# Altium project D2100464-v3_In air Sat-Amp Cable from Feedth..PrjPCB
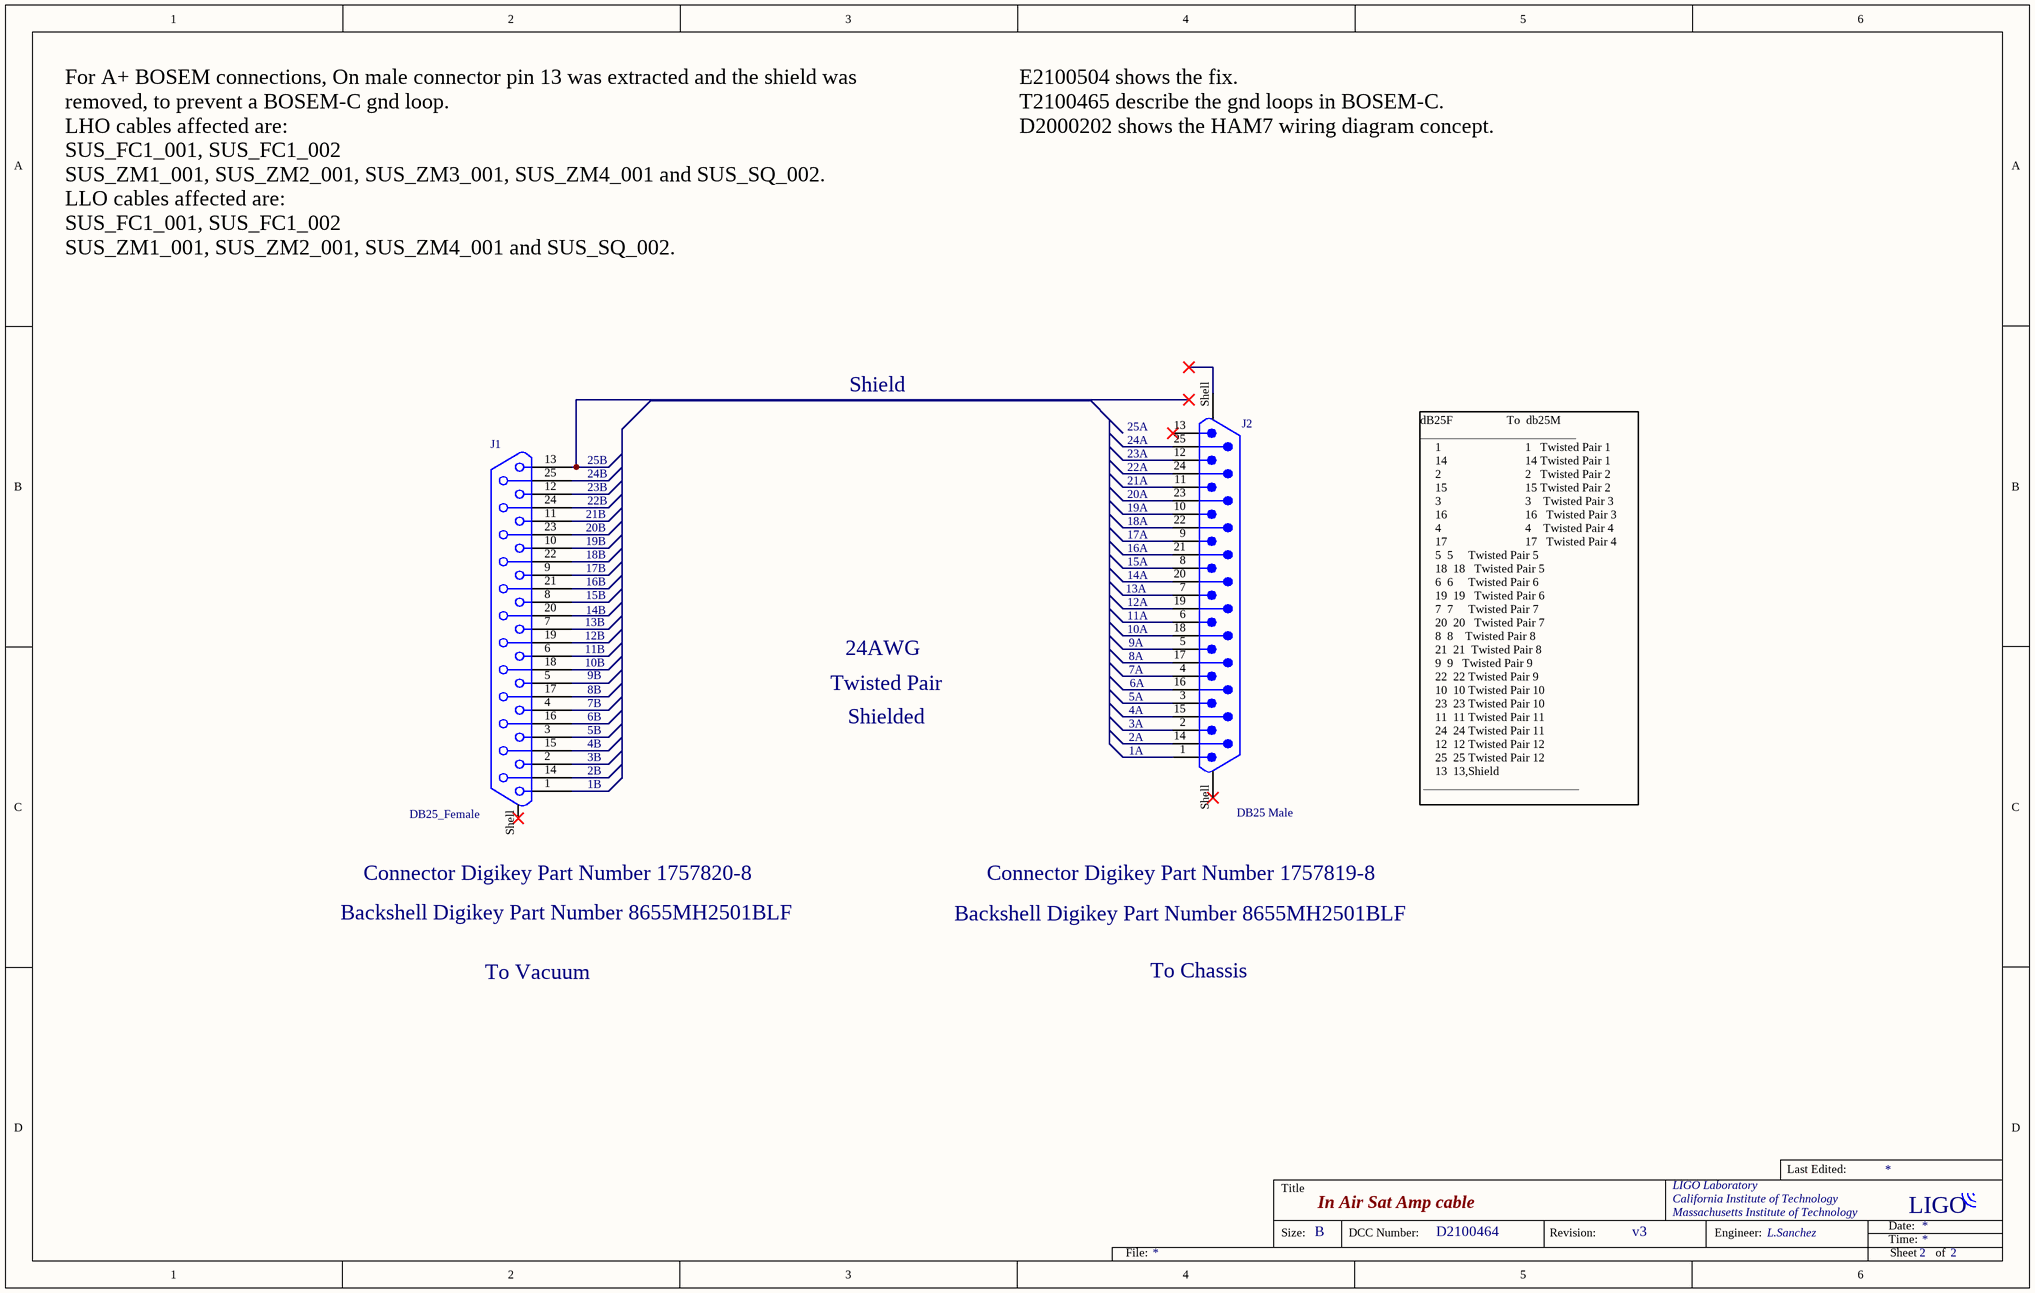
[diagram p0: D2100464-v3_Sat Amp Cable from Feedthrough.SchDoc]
1 sheet, 2 parts. Net scope: global (net labels, ports and power ports of the same name join across sheets).

## Sheet D2100464-v3_Sat Amp Cable from Feedthrough.SchDoc: In Air Sat Amp cable
size B; Organization: LIGO Laboratory; Address1: California Institute of Technology; Address2: Massachusetts Institute of Technology; DocumentNumber: D2100464; Revision: v3; SheetNumber: 2; SheetTotal: 2; Engineer: L.Sanchez

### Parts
J1  DB25_Female  [DB25]
J2  value DB25 Male  (hidden comment: CONN D-SUB PLUG 25POS R/A SOLDER)

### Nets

Not connected (* = marked no-connect by the designer): J1 1 2 3 4 5 6 7 8 9 10 11 12 13* 14 15 16 17 18 19 20 21 22 23 24 25 Shell*; J2 1 2 3 4 5 6 7 8 9 10 11 12 13* 14 15 16 17 18 19 20 21 22 23 24 25 Shell(Shield)*

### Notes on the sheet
- E2100504 shows the fix.
  T2100465 describe the gnd loops in BOSEM-C.
  D2000202 shows the HAM7 wiring diagram concept.
- For A+ BOSEM connections, On male connector pin 13 was extracted and the shield was removed, to prevent a BOSEM-C gnd loop.
  LHO cables affected are:
  SUS_FC1_001, SUS_FC1_002
  SUS_ZM1_001, SUS_ZM2_001, SUS_ZM3_001, SUS_ZM4_001 and SUS_SQ_002.
  LLO cables affected are:
  SUS_FC1_001, SUS_FC1_002
  SUS_ZM1_001, SUS_ZM2_001, SUS_ZM4_001 and SUS_SQ_002.
- Shield
- 25A
- 23B
- 24B
- 22B
- 25B
- 20A
- 22A
- 21A
- 24A
- 23A
- 17B
- 18B
- 20B
- 21B
- 19B
- 16A
- 15A
- 18A
- 17A
- 19A
- (near J1) 12B
- (near J1) 13B
- 14B
- 15B
- 16B
- 13A
- 10A
- 12A
- 11A
- 14A
- (near J1) 11B
- (near J1) 10B
- 8B
- 9B
- 7B
- Twisted Pair
- 24AWG
- 5A
- 8A
- 7A
- 9A
- 6A
- 2B
- 3B
- 5B
- 6B
- 4B
- Shielded
- 2A
- 1A
- 4A
- 3A
- 1B
- dB25F                  To  db25M
  __________________________
  1                            1   Twisted Pair 1
  14                          14 Twisted Pair 1
  2                            2   Twisted Pair 2
  15                          15 Twisted Pair 2
  3                            3    Twisted Pair 3
  16                          16   Twisted Pair 3
  4                            4    Twisted Pair 4
  17                          17   Twisted Pair 4
  5		5     Twisted Pair 5
  18		18   Twisted Pair 5
  6		6     Twisted Pair 6
  19		19   Twisted Pair 6
  7		7     Twisted Pair 7
  20		20   Twisted Pair 7
  8		8    Twisted Pair 8
  21		21  Twisted Pair 8
  9		9   Twisted Pair 9
  22		22 Twisted Pair 9
  10		10 Twisted Pair 10
  23		23 Twisted Pair 10
  11		11 Twisted Pair 11
  24		24 Twisted Pair 11
  12		12 Twisted Pair 12
  25		25 Twisted Pair 12
  13		13,Shield
  __________________________
- Connector Digikey Part Number 1757820-8
- Connector Digikey Part Number 1757819-8
- Backshell Digikey Part Number 8655MH2501BLF
- To Vacuum
- To Chassis

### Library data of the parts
J2 = DB25M_Shell: Manufacturers Part Number: 182-025-113R531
